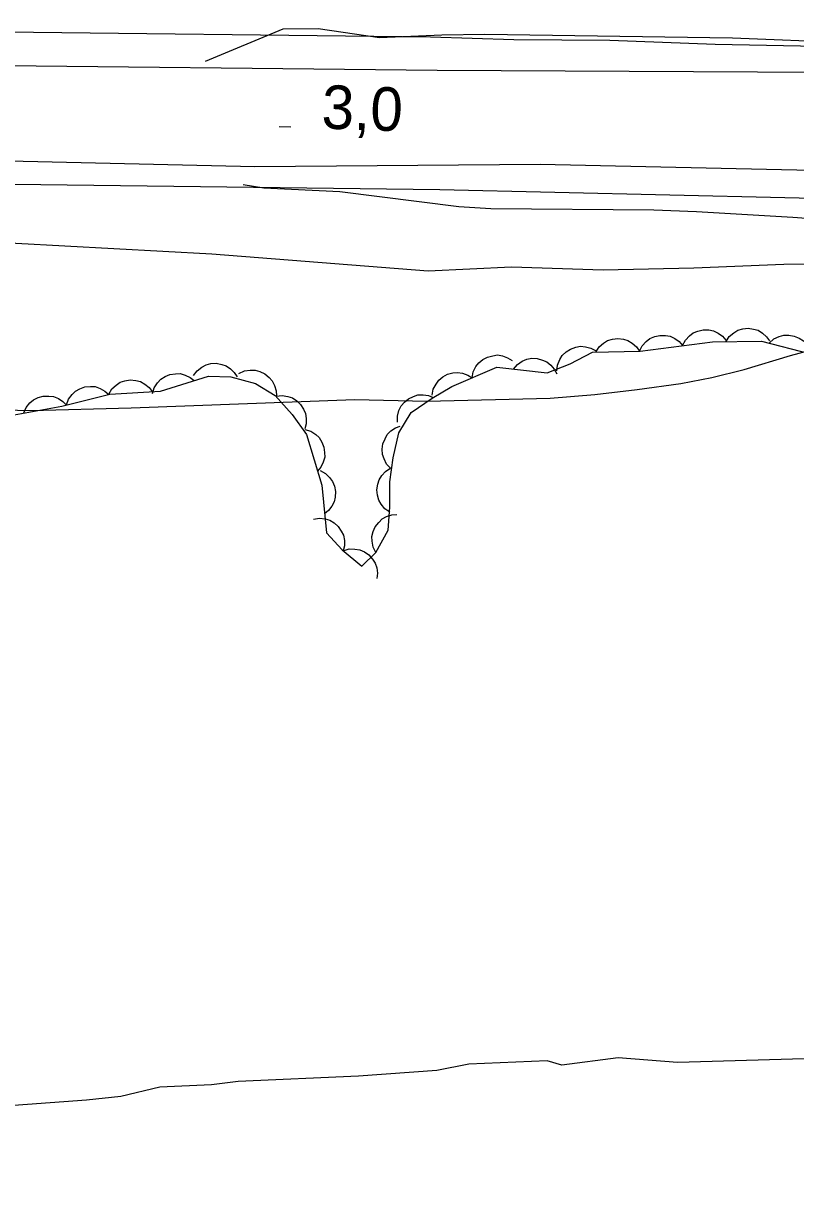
# Model space of a CAD drawing. Extents: x 336540 to 340074, y 5572036 to 5573747.
# Drawn here: x 337682.8 to 337736, y 5572521.1 to 5572601.6 of the extents above; entities that cross this region are included whole.
import ezdxf

# ---------------------------------------------------------------- set-up
doc = ezdxf.new("R2010")
doc.units = 0
for name, color, linetype in [('Niveau 2', 7, 'Continuous'), ('Niveau 21', 7, 'Continuous'), ('Niveau 22', 7, 'Continuous'), ('Niveau 3', 7, 'Continuous'), ('Niveau 44', 7, 'Continuous')]:
    doc.layers.add(name, color=color, linetype=linetype)

msp = doc.modelspace()

# ---------------------------------------------------------------- linework, layer by layer
at = {"layer": 'Niveau 2'}
for points in [[(337695.38, 5572599), (337700.72, 5572601.23), (337703.13, 5572601.26), (337707.34, 5572600.63), (337711.64, 5572600.82), (337714.6, 5572600.86), (337731.65, 5572600.62), (337739.66, 5572600.3)], [(337756.53, 5572584.69), (337758.7, 5572585.19), (337760.88, 5572585.57), (337767.78, 5572585.81), (337770.23, 5572586.04), (337772.4, 5572586.71), (337772.2, 5572587.03), (337771.41, 5572587.24), (337764.38, 5572587.01), (337745.51, 5572587.53), (337735.8, 5572588.24), (337729.16, 5572588.63), (337726.24, 5572588.75), (337715.02, 5572588.84), (337712.8, 5572588.98), (337704.62, 5572590.02), (337699.4, 5572590.28), (337697.97, 5572590.49)], [(337680.61, 5572575.03), (337683.36, 5572574.97), (337690.25, 5572575.15), (337705.66, 5572575.73), (337710.6, 5572575.61), (337719.09, 5572575.82), (337722.17, 5572576.07), (337725.09, 5572576.41), (337728.08, 5572576.82), (337730.23, 5572577.23), (337732.45, 5572577.79), (337735.64, 5572578.75), (337741.07, 5572580.23)]]:
    msp.add_lwpolyline(points, dxfattribs=at)
at = {"layer": 'Niveau 21'}
for points in [[(337420.85, 5572589.04), (337469.47, 5572594.26), (337480.57, 5572595.33), (337515.42, 5572597.98), (337535, 5572599.61), (337544.58, 5572600.19), (337550.06, 5572600.38), (337598.2, 5572601.54), (337614.52, 5572601.61), (337655.5, 5572601.49), (337679.62, 5572601.06), (337710.85, 5572600.68), (337716.59, 5572600.49), (337723.21, 5572600.45), (337730.46, 5572600.17), (337746.92, 5572599.86)], [(337742.17, 5572598.21), (337711.32, 5572598.36), (337677.31, 5572598.73), (337652.3, 5572599.16), (337611.58, 5572599.51), (337600.96, 5572599.42), (337574.84, 5572598.81), (337564.55, 5572598.53), (337551.87, 5572598.05), (337542.02, 5572597.49), (337498.93, 5572594.53), (337485.96, 5572593.4), (337475.89, 5572592.36), (337426.83, 5572587.03)], [(337352.94, 5572571.52), (337383.95, 5572575.87), (337413.72, 5572579.71), (337461.55, 5572584.84), (337526.62, 5572590.2), (337543.66, 5572591.12), (337577.94, 5572592.61), (337610.08, 5572593.14), (337670.84, 5572592.4), (337698.78, 5572591.75), (337718.4, 5572591.92), (337765.14, 5572590.89)], [(337443.52, 5572580.72), (337457.51, 5572582.4), (337473.74, 5572584.23), (337486.38, 5572585.46), (337497.48, 5572586.37), (337528.02, 5572588.55), (337549.85, 5572589.91), (337567.34, 5572590.63), (337583.41, 5572591.15), (337595.91, 5572591.37), (337605.15, 5572591.37), (337627.52, 5572590.98), (337656.05, 5572590.97), (337680.34, 5572590.56), (337711.5, 5572590.18), (337758.99, 5572589.08)]]:
    msp.add_lwpolyline(points, dxfattribs=at)
at = {"layer": 'Niveau 22'}
for points in [[(337617.64, 5572586.32), (337626.1, 5572586.56), (337650.09, 5572586.79), (337655.92, 5572586.59), (337661.9, 5572586.55), (337673.68, 5572586.31), (337679.55, 5572586.5), (337682.33, 5572586.48), (337695.82, 5572585.75), (337710.71, 5572584.59), (337716.44, 5572584.85), (337722.74, 5572584.66), (337728.98, 5572584.78), (337735.18, 5572585.05), (337740.87, 5572585.09)], [(337738.17, 5572530.4), (337727.86, 5572530.11), (337723.77, 5572530.43), (337719.91, 5572529.92), (337718.89, 5572530.22), (337713.49, 5572529.99), (337711.3, 5572529.55), (337705.9, 5572529.16), (337697.62, 5572528.8), (337695.79, 5572528.56), (337692.22, 5572528.4), (337689.54, 5572527.76), (337687.19, 5572527.5), (337680.61, 5572527.03), (337678.43, 5572526.44), (337669.36, 5572525.36), (337665.81, 5572524.86), (337663.48, 5572524.1), (337655.06, 5572523.05), (337652.56, 5572522.44), (337648.5, 5572522.26), (337646.65, 5572521.84), (337639.61, 5572520.69)]]:
    msp.add_lwpolyline(points, dxfattribs=at)
at = {"layer": 'Niveau 3'}
msp.add_line((337700.45, 5572594.52), (337701.25, 5572594.48), dxfattribs=at)
at = {"layer": 'Niveau 44'}
for points in [[(337725.24, 5572579.05), (337725.43, 5572579.43), (337725.71, 5572579.72), (337725.96, 5572579.93), (337726.29, 5572580.06), (337726.65, 5572580.14), (337727.03, 5572580.12), (337727.36, 5572580.08), (337727.67, 5572579.92), (337727.97, 5572579.71), (337728.21, 5572579.44)], [(337728.21, 5572579.44), (337728.4, 5572579.81), (337728.68, 5572580.1), (337728.94, 5572580.31), (337729.26, 5572580.44), (337729.63, 5572580.52), (337730.01, 5572580.51), (337730.33, 5572580.46), (337730.65, 5572580.3), (337730.95, 5572580.09), (337731.19, 5572579.82)], [(337731.2, 5572579.71), (337731.42, 5572580.06), (337731.74, 5572580.32), (337732.02, 5572580.5), (337732.35, 5572580.59), (337732.72, 5572580.63), (337733.1, 5572580.57), (337733.42, 5572580.49), (337733.71, 5572580.3), (337733.99, 5572580.05), (337734.2, 5572579.76)], [(337734.18, 5572579.61), (337734.49, 5572579.89), (337734.86, 5572580.06), (337735.18, 5572580.15), (337735.53, 5572580.16), (337735.89, 5572580.09), (337736.24, 5572579.94), (337736.53, 5572579.77), (337736.76, 5572579.51), (337736.96, 5572579.2), (337737.08, 5572578.86)], [(337682.21, 5572574.68), (337685.48, 5572575.27), (337688.78, 5572576.09), (337692.28, 5572576.3), (337695.58, 5572577.34), (337697.12, 5572577.29), (337698.81, 5572576.83), (337700.18, 5572576.01), (337701.34, 5572574.69), (337702.33, 5572573.32), (337703.37, 5572569.84), (337703.7, 5572566.54), (337704.79, 5572565.37), (337706.14, 5572564.26), (337707.1, 5572565.2), (337707.95, 5572566.73), (337708.07, 5572568.31), (337708.07, 5572570.06), (337708.29, 5572571.72), (337708.67, 5572573.43), (337709.53, 5572574.82), (337710.97, 5572575.81), (337712.33, 5572576.61), (337715.42, 5572577.95), (337718.9, 5572577.57), (337720.47, 5572578.17), (337722.01, 5572578.99), (337725.3, 5572579.06), (337730.26, 5572579.7), (337733.65, 5572579.75), (337737.01, 5572578.88)], [(337719.56, 5572577.69), (337719.61, 5572578.1), (337719.77, 5572578.48), (337719.93, 5572578.76), (337720.19, 5572579), (337720.5, 5572579.2), (337720.86, 5572579.32), (337721.18, 5572579.39), (337721.53, 5572579.36), (337721.89, 5572579.27), (337722.21, 5572579.1)], [(337722.24, 5572578.99), (337722.46, 5572579.35), (337722.77, 5572579.61), (337723.05, 5572579.79), (337723.39, 5572579.88), (337723.76, 5572579.92), (337724.14, 5572579.87), (337724.45, 5572579.79), (337724.75, 5572579.6), (337725.03, 5572579.35), (337725.24, 5572579.06)], [(337713.73, 5572577.22), (337713.8, 5572577.63), (337713.99, 5572577.99), (337714.18, 5572578.26), (337714.46, 5572578.47), (337714.78, 5572578.65), (337715.15, 5572578.74), (337715.48, 5572578.79), (337715.82, 5572578.73), (337716.17, 5572578.6), (337716.48, 5572578.41)], [(337716.57, 5572577.82), (337716.84, 5572578.14), (337717.18, 5572578.36), (337717.48, 5572578.5), (337717.83, 5572578.56), (337718.2, 5572578.55), (337718.56, 5572578.44), (337718.87, 5572578.32), (337719.14, 5572578.1), (337719.38, 5572577.82), (337719.55, 5572577.5)], [(337694.55, 5572577.37), (337694.79, 5572577.71), (337695.12, 5572577.96), (337695.41, 5572578.12), (337695.75, 5572578.2), (337696.12, 5572578.22), (337696.49, 5572578.14), (337696.8, 5572578.04), (337697.09, 5572577.84), (337697.35, 5572577.58), (337697.55, 5572577.28)], [(337697.67, 5572577.51), (337698.05, 5572577.69), (337698.45, 5572577.74), (337698.79, 5572577.75), (337699.12, 5572577.65), (337699.46, 5572577.49), (337699.75, 5572577.24), (337699.97, 5572577), (337700.12, 5572576.68), (337700.23, 5572576.33), (337700.25, 5572575.97)], [(337688.71, 5572576.09), (337688.93, 5572576.45), (337689.23, 5572576.72), (337689.5, 5572576.91), (337689.83, 5572577.02), (337690.2, 5572577.07), (337690.58, 5572577.03), (337690.9, 5572576.96), (337691.2, 5572576.79), (337691.49, 5572576.55), (337691.71, 5572576.27)], [(337691.73, 5572576.13), (337691.85, 5572576.53), (337692.08, 5572576.87), (337692.3, 5572577.12), (337692.59, 5572577.3), (337692.93, 5572577.45), (337693.31, 5572577.5), (337693.64, 5572577.51), (337693.98, 5572577.41), (337694.31, 5572577.25), (337694.6, 5572577.03)], [(337710.97, 5572576.02), (337711.05, 5572576.43), (337711.24, 5572576.79), (337711.43, 5572577.06), (337711.71, 5572577.28), (337712.03, 5572577.46), (337712.4, 5572577.55), (337712.73, 5572577.59), (337713.07, 5572577.53), (337713.42, 5572577.41), (337713.73, 5572577.22)], [(337685.8, 5572575.35), (337685.95, 5572575.74), (337686.19, 5572576.07), (337686.43, 5572576.3), (337686.73, 5572576.47), (337687.08, 5572576.59), (337687.47, 5572576.62), (337687.79, 5572576.61), (337688.12, 5572576.49), (337688.45, 5572576.31), (337688.72, 5572576.07)], [(337700.23, 5572575.95), (337700.65, 5572576), (337701.05, 5572575.93), (337701.36, 5572575.84), (337701.65, 5572575.64), (337701.92, 5572575.39), (337702.12, 5572575.06), (337702.26, 5572574.77), (337702.31, 5572574.42), (337702.3, 5572574.05), (337702.21, 5572573.7)], [(337708.58, 5572574.17), (337708.58, 5572574.58), (337708.69, 5572574.97), (337708.83, 5572575.28), (337709.06, 5572575.54), (337709.34, 5572575.78), (337709.69, 5572575.94), (337710, 5572576.04), (337710.35, 5572576.05), (337710.72, 5572576), (337711.05, 5572575.87)], [(337682.86, 5572574.8), (337683.03, 5572575.18), (337683.29, 5572575.49), (337683.54, 5572575.71), (337683.86, 5572575.86), (337684.21, 5572575.95), (337684.6, 5572575.96), (337684.92, 5572575.93), (337685.25, 5572575.79), (337685.56, 5572575.59), (337685.81, 5572575.33)], [(337702.22, 5572573.67), (337702.62, 5572573.55), (337702.96, 5572573.32), (337703.2, 5572573.1), (337703.39, 5572572.8), (337703.52, 5572572.45), (337703.57, 5572572.07), (337703.58, 5572571.75), (337703.47, 5572571.41), (337703.31, 5572571.08), (337703.08, 5572570.8)], [(337708.12, 5572570.97), (337707.84, 5572571.28), (337707.66, 5572571.64), (337707.55, 5572571.95), (337707.53, 5572572.3), (337707.58, 5572572.67), (337707.73, 5572573.02), (337707.88, 5572573.31), (337708.13, 5572573.56), (337708.44, 5572573.77), (337708.77, 5572573.9)], [(337703.27, 5572570.84), (337703.64, 5572570.64), (337703.92, 5572570.35), (337704.12, 5572570.08), (337704.25, 5572569.76), (337704.32, 5572569.39), (337704.29, 5572569.01), (337704.23, 5572568.69), (337704.07, 5572568.38), (337703.85, 5572568.08), (337703.57, 5572567.85)], [(337708.07, 5572567.97), (337707.72, 5572568.2), (337707.47, 5572568.52), (337707.3, 5572568.8), (337707.21, 5572569.14), (337707.17, 5572569.51), (337707.24, 5572569.89), (337707.33, 5572570.2), (337707.52, 5572570.49), (337707.77, 5572570.77), (337708.07, 5572570.97)], [(337702.8, 5572567.5), (337703.21, 5572567.57), (337703.62, 5572567.51), (337703.94, 5572567.42), (337704.23, 5572567.24), (337704.51, 5572566.99), (337704.72, 5572566.67), (337704.87, 5572566.38), (337704.93, 5572566.03), (337704.93, 5572565.66), (337704.85, 5572565.31)], [(337707.1, 5572565.19), (337706.91, 5572565.57), (337706.84, 5572565.97), (337706.82, 5572566.3), (337706.91, 5572566.64), (337707.06, 5572566.97), (337707.3, 5572567.27), (337707.53, 5572567.51), (337707.84, 5572567.67), (337708.19, 5572567.78), (337708.55, 5572567.82)], [(337704.85, 5572565.32), (337705.26, 5572565.44), (337705.66, 5572565.43), (337705.99, 5572565.39), (337706.31, 5572565.24), (337706.61, 5572565.03), (337706.86, 5572564.74), (337707.05, 5572564.47), (337707.16, 5572564.14), (337707.21, 5572563.77), (337707.17, 5572563.41)]]:
    msp.add_lwpolyline(points, dxfattribs=at)

# ---------------------------------------------------------------- texts
at = {"layer": 'Niveau 3'}
msp.add_text('3,0    ', height=2.9999, rotation=357.89647, dxfattribs=at).set_placement((337703.33, 5572594.38))

doc.saveas('drawing.dxf')
